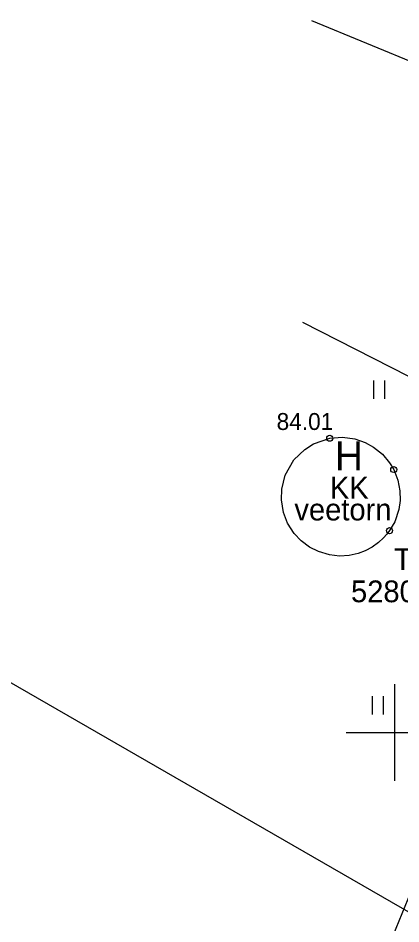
# Model space of a CAD drawing. Extents: x 648748 to 649126, y 6457789 to 6458252.
# Drawn here: x 648884.43 to 648900.26, y 6458192.08 to 6458229.55 of the extents above; entities that cross this region are included whole.
import ezdxf

# ---------------------------------------------------------------- set-up
doc = ezdxf.new("R2010")
doc.units = 0
for name, color, linetype in [('HALJASTUS', 7, 'Continuous'), ('HOONE', 7, 'Continuous'), ('KORGUS-EH2000', 7, 'Continuous'), ('PIIR', 7, 'Continuous'), ('SITRASS', 7, 'Continuous'), ('VORK', 7, 'Continuous'), ('VTRASS', 7, 'Continuous')]:
    doc.layers.add(name, color=color, linetype=linetype)

msp = doc.modelspace()

# ---------------------------------------------------------------- linework, layer by layer
at = {"layer": 'HALJASTUS'}
for p, q in [((648899.132, 6458214.564), (648899.132, 6458213.803)), ((648899.587, 6458214.564), (648899.587, 6458213.803)), ((648899.076, 6458201.507), (648899.076, 6458200.746)), ((648899.531, 6458201.507), (648899.531, 6458200.746))]:
    msp.add_line(p, q, dxfattribs=at)
at = {"layer": 'HOONE'}
msp.add_lwpolyline([(648897.318, 6458212.173), (648897.838, 6458212.215), (648898.353, 6458212.146), (648898.782, 6458211.993), (648899.132, 6458211.802), (648899.492, 6458211.515), (648899.793, 6458211.159), (648899.962, 6458210.877), (648900.132, 6458210.444), (648900.22, 6458209.996), (648900.226, 6458209.603), (648900.174, 6458209.23), (648900.002, 6458208.72), (648899.789, 6458208.349), (648899.674, 6458208.198), (648899.542, 6458208.049), (648899.33, 6458207.854), (648899.067, 6458207.668), (648898.778, 6458207.513), (648898.488, 6458207.405), (648898.114, 6458207.322), (648897.725, 6458207.299), (648897.308, 6458207.343), (648896.857, 6458207.482), (648896.478, 6458207.67), (648896.132, 6458207.926), (648895.847, 6458208.229), (648895.574, 6458208.658), (648895.408, 6458209.098), (648895.318, 6458209.624), (648895.334, 6458210.07), (648895.478, 6458210.64), (648895.837, 6458211.272), (648896.288, 6458211.713), (648896.646, 6458211.942), (648897.318, 6458212.173)], dxfattribs=at)
at = {"layer": 'KORGUS-EH2000'}
for centre in [(648897.318, 6458212.173), (648899.962, 6458210.877), (648899.789, 6458208.349)]:
    msp.add_circle(centre, 0.125, dxfattribs=at)
at = {"layer": 'PIIR'}
for p, q in [((648906.45, 6458225.36), (648896.582, 6458229.443)), ((648882.169, 6458203.173), (648904.5, 6458190.31))]:
    msp.add_line(p, q, dxfattribs=at)
at = {"layer": 'SITRASS'}
msp.add_lwpolyline([(648920.046, 6458238.741), (648918.974, 6458235.501), (648918.374, 6458231.362), (648916.343, 6458227.563), (648914.757, 6458225.445), (648913.89, 6458223.662), (648910.648, 6458217.515), (648906.266, 6458207.122), (648902.537, 6458197.956), (648897.439, 6458185.518), (648896.343, 6458186.017)], dxfattribs=at)
at = {"layer": 'VORK'}
for p, q in [((648900, 6458202), (648900, 6458198)), ((648898, 6458200), (648902, 6458200))]:
    msp.add_line(p, q, dxfattribs=at)
at = {"layer": 'VTRASS'}
msp.add_lwpolyline([(648896.188, 6458216.971), (648904.231, 6458212.879)], dxfattribs=at)

# ---------------------------------------------------------------- texts
at = {"layer": 'HOONE'}
for s, height, p in [('H', 1.2, (648897.533, 6458210.844)), ('KK', 0.9, (648897.319, 6458209.676)), ('veetorn', 0.9, (648895.855, 6458208.772))]:
    msp.add_text(s, height=height, dxfattribs=at).set_placement(p)
at = {"layer": 'KORGUS-EH2000'}
msp.add_text('84.01', height=0.7, dxfattribs=at).set_placement((648895.12, 6458212.514))
at = {"layer": 'PIIR'}
for s, p in [('Tamsa tn 1', (648899.972, 6458206.723)), ('52801:009:0098', (648898.197, 6458205.388))]:
    msp.add_text(s, height=0.9, rotation=0, dxfattribs=at).set_placement(p)

doc.saveas('drawing.dxf')
